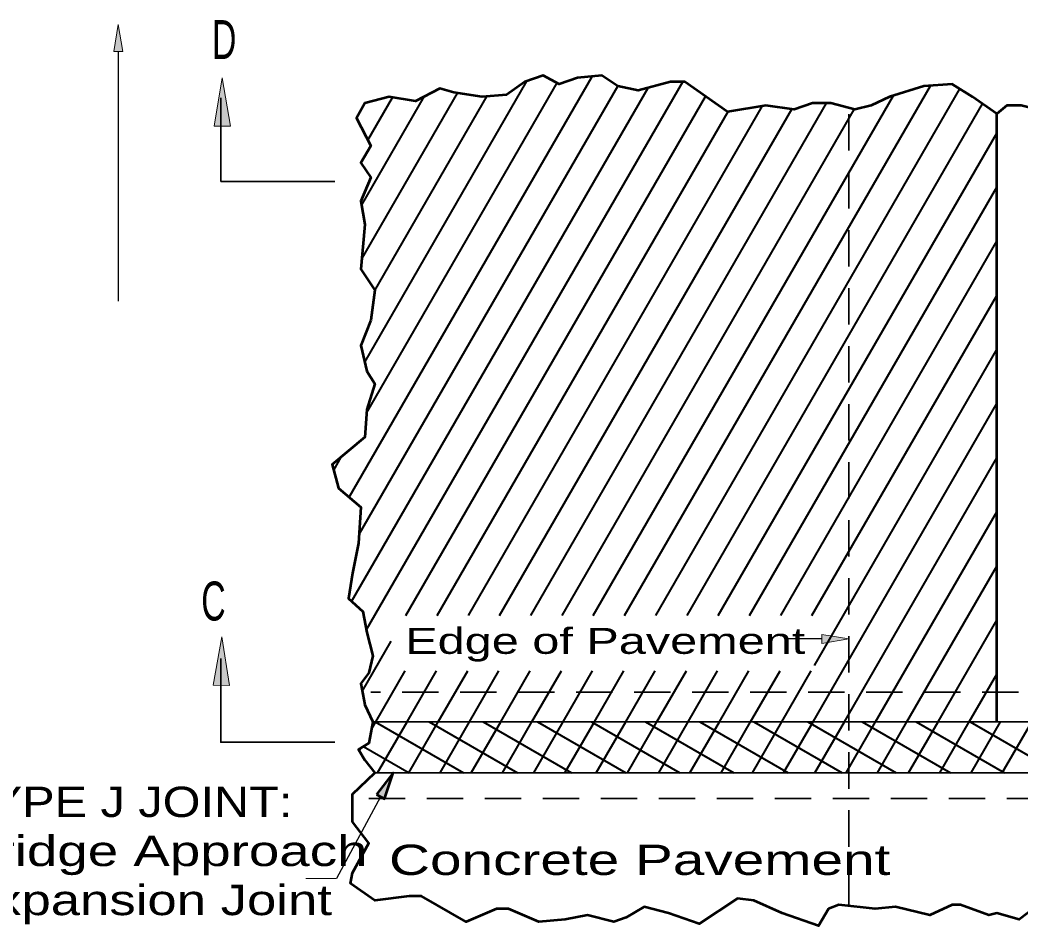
# Model space of a CAD drawing. Extents: x 14 to 49.3, y 28 to 50.
# Drawn here: x 24.379 to 29.004, y 42.279 to 46.464 of the extents above; entities that cross this region are included whole.
import ezdxf

# ---------------------------------------------------------------- set-up
doc = ezdxf.new("R2010")
doc.units = 0
doc.header["$LTSCALE"] = 0.056
doc.linetypes.add('MEDIUM_DASHED', pattern=[4.5, 3, -1.5])
for name, color, linetype, lineweight in [('1', 7, 'Continuous', 35), ('2', 7, 'MEDIUM_DASHED', 35), ('3', 7, 'Continuous', 13), ('5', 7, 'Continuous', 35)]:
    doc.layers.add(name, color=color, linetype=linetype, lineweight=lineweight)

msp = doc.modelspace()

# ---------------------------------------------------------------- hatches: boundary and pattern name
at = {"layer": '3'}
for points in [[(24.81175, 46.3185), (24.8535, 46.3185), (24.83267, 46.4435), (24.83267, 46.4435)], [(25.27608, 45.97308), (25.35092, 45.97375), (25.31208, 46.19775), (25.31208, 46.19775)], [(25.34633, 43.39033), (25.2715, 43.391), (25.31033, 43.615), (25.31033, 43.615)], [(28.0835, 43.62575), (28.0835, 43.58408), (28.2085, 43.60492), (28.2085, 43.60492)], [(26.02525, 42.88592), (26.06192, 42.86625), (26.10275, 42.98625), (26.10275, 42.98625)]]:
    msp.add_hatch(color=256, dxfattribs=at).paths.add_polyline_path(points)

# ---------------------------------------------------------------- linework, layer by layer
at = {"layer": '1', "lineweight": 40}
for p, q in [((25.89958, 44.25942), (27.02208, 46.20367)), ((25.94567, 44.08917), (27.14058, 46.15892)), ((25.971, 44.88308), (26.72067, 46.1815)), ((25.9785, 43.64608), (27.44033, 46.17808)), ((25.97942, 44.64758), (26.86025, 46.17333)), ((27.17183, 43.713), (28.585, 46.16067)), ((25.91075, 43.77867), (27.28017, 46.15058)), ((25.95625, 45.60742), (26.24733, 46.11167)), ((25.95667, 45.35825), (26.40017, 46.12642)), ((26.018, 45.2145), (26.53575, 46.11117)), ((26.1615, 43.713), (27.546, 46.11108)), ((27.0275, 43.713), (28.41433, 46.11508)), ((27.31617, 43.713), (28.72092, 46.14617)), ((25.98617, 45.90933), (26.10008, 46.10667)), ((26.45017, 43.713), (27.8095, 46.0675)), ((26.73883, 43.713), (28.10533, 46.07983)), ((27.4605, 43.713), (28.82542, 46.07717)), ((26.30583, 43.713), (27.64992, 46.04108)), ((26.5945, 43.713), (27.94492, 46.052)), ((26.88317, 43.713), (28.23317, 46.05125)), ((27.60483, 43.713), (28.89175, 45.942)), ((27.74917, 43.713), (28.89175, 45.692)), ((27.8935, 43.713), (28.89175, 45.442)), ((28.03783, 43.713), (28.89175, 45.192)), ((28.04933, 43.48292), (28.89175, 44.942)), ((28.043, 43.22192), (28.89175, 44.692)), ((25.828, 44.38542), (25.8625, 44.44517)), ((28.18733, 43.22192), (28.89175, 44.442)), ((28.33167, 43.22192), (28.89175, 44.192)), ((28.476, 43.22192), (28.89175, 43.942)), ((28.62042, 43.22192), (28.89175, 43.692)), ((25.95942, 43.363), (26.09308, 43.59442)), ((26.02233, 43.22192), (26.15842, 43.45767)), ((26.16667, 43.22192), (26.30275, 43.45767)), ((26.311, 43.22192), (26.44708, 43.45767)), ((26.45533, 43.22192), (26.59142, 43.45767)), ((26.59967, 43.22192), (26.73575, 43.45767)), ((26.744, 43.22192), (26.88008, 43.45767)), ((26.88833, 43.22192), (27.02442, 43.45767)), ((27.03267, 43.22192), (27.16875, 43.45767)), ((27.177, 43.22192), (27.31308, 43.45767)), ((27.32133, 43.22192), (27.45742, 43.45767)), ((27.46567, 43.22192), (27.60175, 43.45767)), ((27.61, 43.22192), (27.74608, 43.45767)), ((27.75433, 43.22192), (27.89042, 43.45767)), ((27.89867, 43.22192), (28.03475, 43.45767)), ((28.76475, 43.22192), (28.89175, 43.442)), ((26.00217, 43.187), (26.02233, 43.22192)), ((26.01908, 43.22192), (26.42733, 42.98625)), ((26.03058, 42.98625), (26.16667, 43.22192)), ((26.17492, 42.98625), (26.311, 43.22192)), ((26.26908, 43.22192), (26.67733, 42.98625)), ((26.31925, 42.98625), (26.45533, 43.22192)), ((26.46358, 42.98625), (26.59967, 43.22192)), ((26.51908, 43.22192), (26.92733, 42.98625)), ((26.60792, 42.98625), (26.744, 43.22192)), ((26.75225, 42.98625), (26.88833, 43.22192)), ((26.76908, 43.22192), (27.17733, 42.98625)), ((26.89658, 42.98625), (27.03267, 43.22192)), ((27.01908, 43.22192), (27.42733, 42.98625)), ((27.04092, 42.98625), (27.177, 43.22192)), ((27.18525, 42.98625), (27.32133, 43.22192)), ((27.26908, 43.22192), (27.67733, 42.98625)), ((27.32958, 42.98625), (27.46567, 43.22192)), ((27.47392, 42.98625), (27.61, 43.22192)), ((27.51908, 43.22192), (27.92733, 42.98625)), ((27.61825, 42.98625), (27.75433, 43.22192)), ((27.76258, 42.98625), (27.89867, 43.22192)), ((27.76908, 43.22192), (28.17733, 42.98625)), ((27.90692, 42.98625), (28.043, 43.22192)), ((28.01908, 43.22192), (28.42733, 42.98625)), ((28.05125, 42.98625), (28.18733, 43.22192)), ((28.19558, 42.98625), (28.33167, 43.22192)), ((28.26908, 43.22192), (28.67733, 42.98625)), ((28.33992, 42.98625), (28.476, 43.22192)), ((28.48425, 42.98625), (28.62042, 43.22192)), ((28.51908, 43.22192), (28.92733, 42.98625)), ((28.62867, 42.98625), (28.76475, 43.22192)), ((28.76908, 43.22192), (29.17733, 42.98625)), ((28.773, 42.98625), (28.90908, 43.22192)), ((28.91733, 42.98625), (29.05342, 43.22192)), ((25.96575, 43.10842), (26.17733, 42.98625)), ((25.94592, 43.08967), (25.95158, 43.0995))]:
    msp.add_line(p, q, dxfattribs=at)
at = {"layer": '1'}
for p, q in [((29.52825, 43.22192), (26.00883, 43.22192)), ((26.01817, 42.98625), (29.52825, 42.98625))]:
    msp.add_line(p, q, dxfattribs=at)
at = {"layer": '1', "lineweight": 53}
for points in [[(28.89175, 43.22192), (28.89175, 46.03075), (28.77942, 46.10933), (28.68583, 46.16825), (28.55483, 46.15842), (28.39567, 46.10933), (28.31142, 46.07), (28.23658, 46.05033), (28.12425, 46.07983), (28.04, 46.07983), (27.95575, 46.05033), (27.82467, 46.07), (27.64683, 46.04058), (27.45025, 46.17808), (27.38475, 46.17808), (27.235, 46.13875), (27.14142, 46.15842), (27.0665, 46.2075), (26.95417, 46.19767), (26.86992, 46.16825), (26.79508, 46.2075), (26.71083, 46.17808), (26.62658, 46.11908), (26.51425, 46.10933), (26.38325, 46.12892), (26.31767, 46.14858), (26.20533, 46.08967), (26.08367, 46.10933), (25.97133, 46.07983), (25.93392, 46.01108), (25.99942, 45.88342), (25.95267, 45.80483), (25.99942, 45.73608), (25.95267, 45.62808), (25.97133, 45.52), (25.95267, 45.31383), (26.01817, 45.21558), (25.99942, 45.07808), (25.95267, 44.96025), (25.98075, 44.84242)], [(29.33175, 42.338), (29.33175, 45.97183), (29.32233, 46.06017), (29.23808, 46.08967), (29.17258, 46.08967), (29.13517, 46.07), (29.079, 46.05033), (29.00408, 46.07), (28.93858, 46.07), (28.89175, 46.03075)], [(25.98075, 44.84242), (26.01817, 44.7835), (25.98075, 44.66558), (25.97133, 44.53792), (25.82158, 44.41025), (25.84967, 44.30225), (25.95267, 44.21383), (25.94325, 44.04692), (25.91517, 43.90942), (25.8965, 43.7915), (25.962, 43.73258), (25.98075, 43.63442), (26.00883, 43.52633), (25.99008, 43.44783), (25.95267, 43.39867), (25.97133, 43.3005), (26.00883, 43.22192)], [(26.00883, 43.22192), (25.99008, 43.12375), (25.94325, 43.09425), (25.97133, 43.04517), (26.01817, 42.98625)], [(29.09767, 42.38717), (28.99475, 42.30858), (28.89175, 42.338), (28.85433, 42.32825), (28.72333, 42.37733), (28.68583, 42.37733), (28.58292, 42.32825), (28.42375, 42.3675), (28.33017, 42.35767), (28.16167, 42.37733), (28.11483, 42.35767), (28.06808, 42.27908), (27.89958, 42.338), (27.7685, 42.39692), (27.69367, 42.40675), (27.51583, 42.28892), (27.37542, 42.338), (27.26308, 42.3675), (27.17883, 42.31842), (27.12267, 42.29875), (27.001, 42.32825), (26.898, 42.30858), (26.77633, 42.29875), (26.63592, 42.35767), (26.57975, 42.35767), (26.43933, 42.29875), (26.23342, 42.41658), (26.17725, 42.41658), (26.01817, 42.39692), (25.90583, 42.4755), (25.91517, 42.52467), (25.99008, 42.66208), (25.91517, 42.76033), (25.91517, 42.888), (26.01817, 42.98625)]]:
    msp.add_lwpolyline(points, dxfattribs=at)
at = {"layer": '2'}
for p, q in [((28.2085, 42.37733), (28.2085, 46.05775)), ((29.52825, 43.35942), (25.99942, 43.35942)), ((25.99008, 42.86833), (29.52825, 42.86833))]:
    msp.add_line(p, q, dxfattribs=at)
at = {"layer": '3', "lineweight": 25}
for p, q in [((24.83267, 46.3185), (24.83267, 45.1655)), ((28.0835, 43.60492), (27.91833, 43.60492)), ((26.04358, 42.87608), (25.84092, 42.49842))]:
    msp.add_line(p, q, dxfattribs=at)
at = {"layer": '3'}
msp.add_line((25.84092, 42.49842), (25.69892, 42.49842), dxfattribs=at)
for points in [[(24.81175, 46.3185), (24.8535, 46.3185), (24.83267, 46.4435), (24.83267, 46.4435)], [(25.27608, 45.97308), (25.35092, 45.97375), (25.31208, 46.19775), (25.31208, 46.19775)], [(25.34633, 43.39033), (25.2715, 43.391), (25.31033, 43.615), (25.31033, 43.615)], [(28.0835, 43.62575), (28.0835, 43.58408), (28.2085, 43.60492), (28.2085, 43.60492)]]:
    msp.add_lwpolyline(points, close=True, dxfattribs=at)
at = {"layer": '3', "lineweight": 53}
msp.add_lwpolyline([(26.02525, 42.88592), (26.06192, 42.86625), (26.10275, 42.98625), (26.10275, 42.98625)], close=True, dxfattribs=at)
at = {"layer": '5'}
for p, q in [((25.30633, 46.10508), (25.30633, 45.71892)), ((25.30633, 45.71892), (25.83258, 45.71892))]:
    msp.add_line(p, q, dxfattribs=at)
msp.add_lwpolyline([(25.30633, 43.51425), (25.30633, 43.12808), (25.83258, 43.12808)], dxfattribs=at)

# ---------------------------------------------------------------- texts
at = {"layer": '3'}
for s, height, width, p in [('Edge of Pavement', 0.12, 1.4, (26.1585, 43.53617)), ('TYPE J JOINT:', 0.14, 1.2, (24.10142, 42.7825)), ('Bridge Approach', 0.14, 1.35, (24.10142, 42.55583)), ('Concrete Pavement', 0.14, 1.4, (26.08358, 42.51483)), ('Expansion Joint', 0.14, 1.3, (24.10142, 42.32917))]:
    msp.add_text(s, height=height, dxfattribs=dict(at, width=width)).set_placement(p)
at = {"layer": '5', "width": 0.65}
for s, p in [('D', (25.26533, 46.28417)), ('C', (25.21592, 43.69033))]:
    msp.add_text(s, height=0.18, dxfattribs=at).set_placement(p)

doc.saveas('drawing.dxf')
